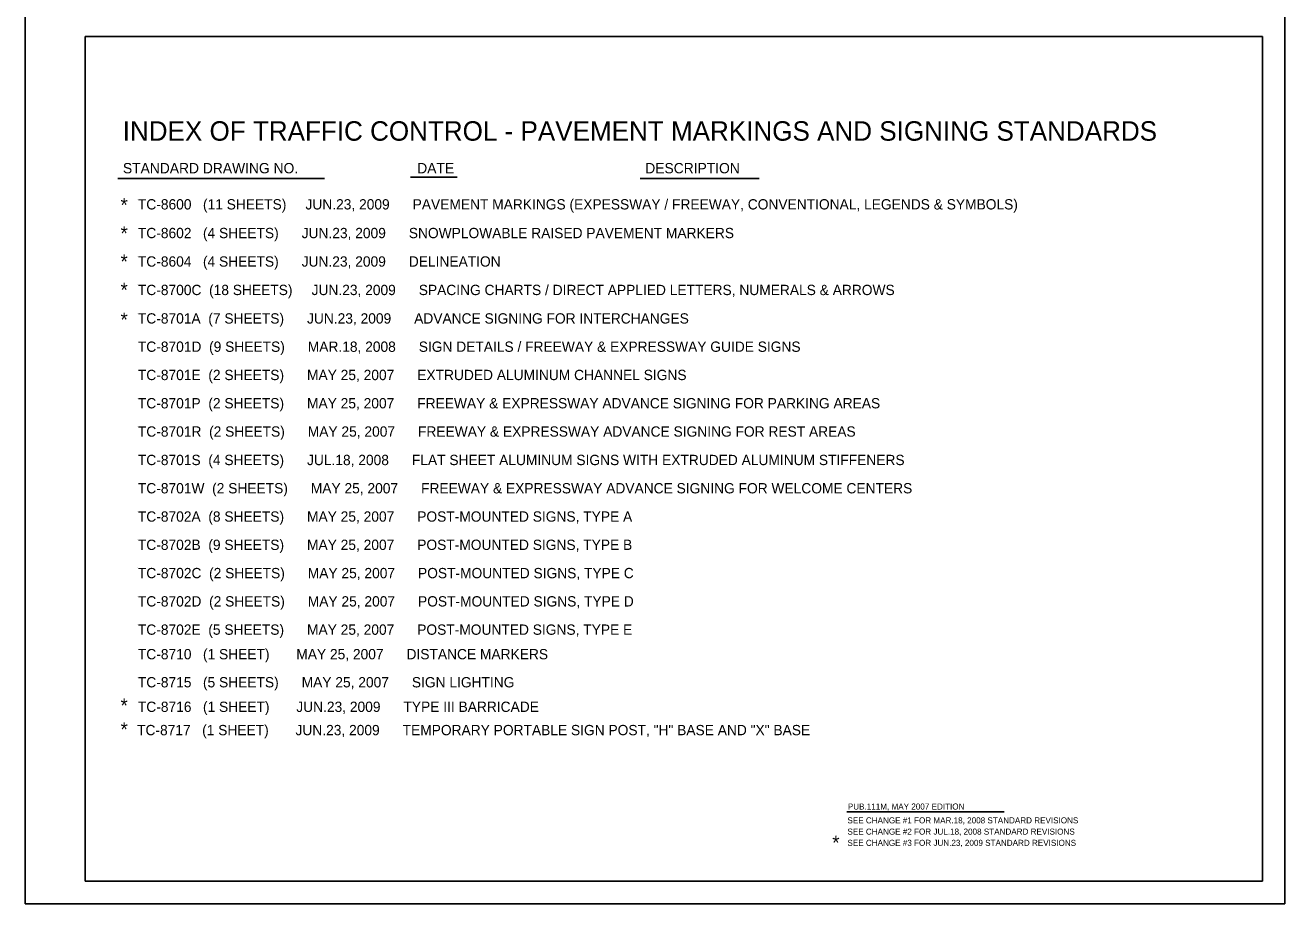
# Model space of a CAD drawing. Extents: x -1746 to -905, y 22 to 1210.
# Drawn here: x -1746 to -905, y 22 to 609 of the extents above; entities that cross this region are included whole.
import ezdxf

# ---------------------------------------------------------------- set-up
doc = ezdxf.new("R2010")
doc.units = 0
for name, color, linetype in [('1', 7, 'Continuous'), ('Level 1', 7, 'Continuous'), ('Level 2', 7, 'Continuous'), ('PLT-BNDY', 7, 'Continuous')]:
    doc.layers.add(name, color=color, linetype=linetype)

msp = doc.modelspace()

# ---------------------------------------------------------------- linework, layer by layer
at = {"layer": '1'}
msp.add_line((-1197.52, 83.48), (-1092.44, 83.48), dxfattribs=at)
at = {"layer": 'Level 1'}
for p, q in [((-1706.14, 601.17), (-920.14, 601.17)), ((-1706.14, 37.17), (-1706.14, 601.17)), ((-920.14, 601.17), (-920.14, 37.17)), ((-920.14, 37.17), (-1706.14, 37.17))]:
    msp.add_line(p, q, dxfattribs=at)
at = {"layer": 'Level 2'}
for p, q in [((-1684.39, 506.28), (-1546.27, 506.28)), ((-1488.89, 507.28), (-1457.77, 507.28)), ((-1335.52, 506.28), (-1256.14, 506.28)), ((-1670.89, 492.53), (-1670.89, 492.53)), ((-1670.89, 454.38), (-1670.89, 454.38)), ((-1670.89, 435.38), (-1670.89, 435.38)), ((-1670.89, 416.5), (-1670.89, 416.5)), ((-1670.89, 359.75), (-1670.89, 359.75)), ((-1670.89, 340.88), (-1670.89, 340.88)), ((-1670.89, 284.25), (-1670.89, 284.25)), ((-1670.89, 265.25), (-1670.89, 265.25)), ((-1670.89, 246.38), (-1670.89, 246.38)), ((-1670.89, 227.5), (-1670.89, 227.5)), ((-1670.89, 208.63), (-1670.89, 208.63)), ((-1670.89, 173.5), (-1670.89, 173.5))]:
    msp.add_line(p, q, dxfattribs=at)
at = {"layer": 'PLT-BNDY'}
msp.add_lwpolyline([(-1746.14, 616.17), (-905.14, 616.17), (-905.14, 22.17), (-1746.14, 22.17)], close=True, dxfattribs=at)

# ---------------------------------------------------------------- texts
at = {"layer": '1'}
for s, height, p in [('*', 9.32, (-1682.48, 484.03)), ('*', 9.32, (-1682.48, 465.11)), ('*', 9.32, (-1682.48, 446.3)), ('*', 9.32, (-1682.48, 427.37)), ('*', 9.32, (-1682.48, 407.49)), ('*', 9.32, (-1682.48, 149.9)), ('*', 9.32, (-1682.48, 133.99)), ('PUB.111M, MAY 2007 EDITION', 4.044, (-1196.89, 85.08)), ('SEE CHANGE #1 FOR MAR.18, 2008 STANDARD REVISIONS', 4.044, (-1197.16, 75.85)), ('SEE CHANGE #2 FOR JUL.18, 2008 STANDARD REVISIONS', 4.044, (-1197.16, 68.34)), ('SEE CHANGE #3 FOR JUN.23, 2009 STANDARD REVISIONS', 4.044, (-1197.16, 60.84))]:
    msp.add_text(s, height=height, dxfattribs=at).set_placement(p)
msp.add_text('*', height=9.32, rotation=360, dxfattribs=at).set_placement((-1207.3, 58.3))
at = {"layer": 'Level 2'}
for s, height, p in [('INDEX OF TRAFFIC CONTROL - PAVEMENT MARKINGS AND SIGNING STANDARDS', 13, (-1681.03, 531.56)), ('STANDARD DRAWING NO.', 6.9067, (-1680.89, 509.78)), ('DATE', 6.907, (-1484.39, 509.78)), ('DESCRIPTION', 6.9067, (-1332.14, 509.78)), ('TC-8600   (11 SHEETS)     JUN.23, 2009      PAVEMENT MARKINGS (EXPESSWAY / FREEWAY, CONVENTIONAL, LEGENDS & SYMBOLS)', 6.87525, (-1670.89, 485.66)), ('TC-8602   (4 SHEETS)      JUN.23, 2009      SNOWPLOWABLE RAISED PAVEMENT MARKERS', 6.8753, (-1670.89, 466.5)), ('TC-8604   (4 SHEETS)      JUN.23, 2009      DELINEATION', 6.8753, (-1670.89, 447.5)), ('TC-8700C  (18 SHEETS)     JUN.23, 2009      SPACING CHARTS / DIRECT APPLIED LETTERS, NUMERALS & ARROWS', 6.87525, (-1670.89, 428.5)), ('TC-8701A  (7 SHEETS)      JUN.23, 2009      ADVANCE SIGNING FOR INTERCHANGES', 6.8753, (-1670.89, 409.5)), ('TC-8701D  (9 SHEETS)      MAR.18, 2008      SIGN DETAILS / FREEWAY & EXPRESSWAY GUIDE SIGNS', 6.8753, (-1670.89, 390.63)), ('TC-8701E  (2 SHEETS)      MAY 25, 2007      EXTRUDED ALUMINUM CHANNEL SIGNS', 6.8753, (-1670.89, 371.75)), ('TC-8701P  (2 SHEETS)      MAY 25, 2007      FREEWAY & EXPRESSWAY ADVANCE SIGNING FOR PARKING AREAS', 6.8753, (-1670.89, 352.88)), ('TC-8701R  (2 SHEETS)      MAY 25, 2007      FREEWAY & EXPRESSWAY ADVANCE SIGNING FOR REST AREAS', 6.8753, (-1670.89, 334)), ('TC-8701S  (4 SHEETS)      JUL.18, 2008      FLAT SHEET ALUMINUM SIGNS WITH EXTRUDED ALUMINUM STIFFENERS', 6.87525, (-1670.89, 315)), ('TC-8701W  (2 SHEETS)      MAY 25, 2007      FREEWAY & EXPRESSWAY ADVANCE SIGNING FOR WELCOME CENTERS', 6.8753, (-1670.89, 296.13)), ('TC-8702A  (8 SHEETS)      MAY 25, 2007      POST-MOUNTED SIGNS, TYPE A', 6.8753, (-1670.89, 277.25)), ('TC-8702B  (9 SHEETS)      MAY 25, 2007      POST-MOUNTED SIGNS, TYPE B', 6.8753, (-1670.89, 258.38)), ('TC-8702C  (2 SHEETS)      MAY 25, 2007      POST-MOUNTED SIGNS, TYPE C', 6.8753, (-1670.89, 239.5)), ('TC-8702D  (2 SHEETS)      MAY 25, 2007      POST-MOUNTED SIGNS, TYPE D', 6.8753, (-1670.89, 220.63)), ('TC-8702E  (5 SHEETS)      MAY 25, 2007      POST-MOUNTED SIGNS, TYPE E', 6.8753, (-1670.89, 201.75)), ('TC-8710   (1 SHEET)       MAY 25, 2007      DISTANCE MARKERS', 6.8753, (-1670.89, 185.38)), ('TC-8715   (5 SHEETS)      MAY 25, 2007      SIGN LIGHTING', 6.8753, (-1670.89, 166.63)), ('TC-8716   (1 SHEET)       JUN.23, 2009      TYPE III BARRICADE', 6.8753, (-1670.89, 150.25)), ('TC-8717   (1 SHEET)       JUN.23, 2009      TEMPORARY PORTABLE SIGN POST, "H" BASE AND "X" BASE', 6.8753, (-1671.43, 134.7))]:
    msp.add_text(s, height=height, dxfattribs=at).set_placement(p)

doc.saveas('drawing.dxf')
